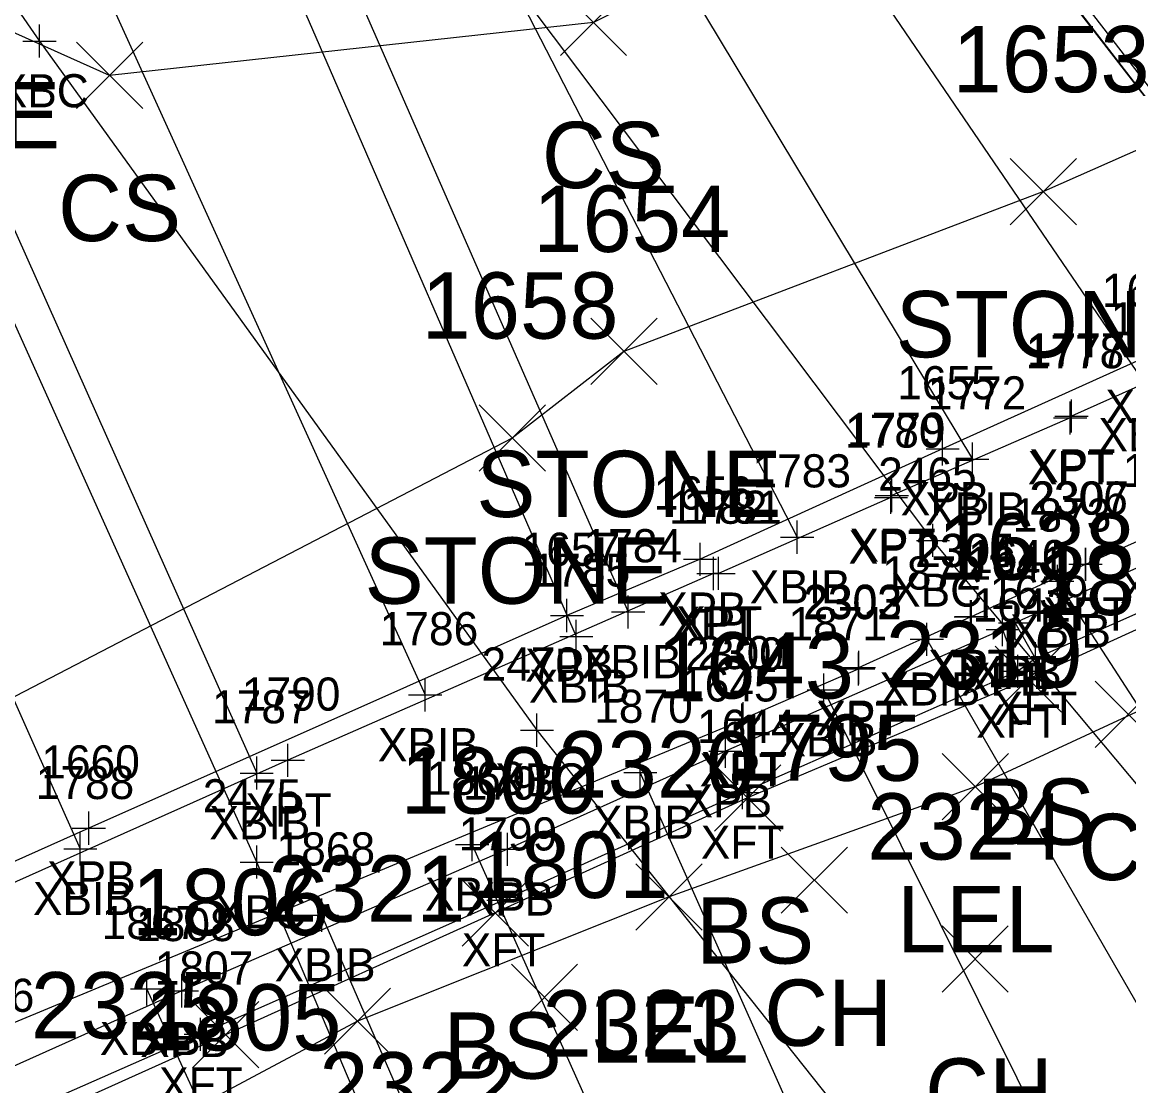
# Model space of a CAD drawing. Extents: x 1504228 to 1506103, y 437717 to 440106.
# Drawn here: x 1505201.55 to 1505234.96, y 438181.79 to 438213.89 of the extents above; entities that cross this region are included whole.
import ezdxf

# ---------------------------------------------------------------- set-up
doc = ezdxf.new("R2010")
doc.units = 0
for name, color, linetype in [('B_A', 7, 'Continuous'), ('B_I', 7, 'Continuous'), ('B_TIC', 7, 'Continuous'), ('BB', 7, 'Continuous'), ('BDC', 7, 'Continuous'), ('BELB', 7, 'Continuous'), ('BFT', 7, 'Continuous'), ('BSUBM', 7, 'Continuous'), ('L_A', 7, 'Continuous'), ('L_I', 7, 'Continuous'), ('L_TIC', 7, 'Continuous'), ('LARO', 7, 'Continuous'), ('LASF', 7, 'Continuous'), ('LELB', 7, 'Continuous')]:
    doc.layers.add(name, color=color, linetype=linetype)

msp = doc.modelspace()

# ---------------------------------------------------------------- linework, layer by layer
at = {"layer": 'B_TIC'}
for p, q in [((1505202.078, 438213.317), (1505202.153, 438213.317)), ((1505233.19, 438201.942), (1505233.265, 438201.942)), ((1505233.226, 438201.999), (1505233.302, 438201.999)), ((1505229.338, 438201.006), (1505229.414, 438201.006)), ((1505230.236, 438200.699), (1505230.311, 438200.699)), ((1505227.78, 438199.546), (1505227.855, 438199.546)), ((1505227.805, 438199.602), (1505227.88, 438199.602)), ((1505224.945, 438198.346), (1505225.021, 438198.346)), ((1505229.046, 438198.247), (1505229.121, 438198.247)), ((1505222.016, 438197.676), (1505222.092, 438197.676)), ((1505233.651, 438197.525), (1505233.726, 438197.525)), ((1505233.658, 438197.526), (1505233.733, 438197.526)), ((1505222.421, 438197.249), (1505222.497, 438197.249)), ((1505222.575, 438197.253), (1505222.651, 438197.253)), ((1505232.802, 438197.013), (1505232.877, 438197.013)), ((1505218, 438195.981), (1505218.075, 438195.981)), ((1505219.845, 438196.087), (1505219.921, 438196.087)), ((1505230.181, 438195.942), (1505230.257, 438195.942)), ((1505230.206, 438195.946), (1505230.282, 438195.946)), ((1505231.149, 438195.559), (1505231.225, 438195.559)), ((1505231.149, 438195.559), (1505231.225, 438195.559)), ((1505231.524, 438195.759), (1505231.599, 438195.759)), ((1505231.524, 438195.759), (1505231.599, 438195.759)), ((1505218.279, 438195.351), (1505218.355, 438195.351)), ((1505228.861, 438195.264), (1505228.936, 438195.264)), ((1505232.137, 438194.68), (1505232.212, 438194.68)), ((1505232.137, 438194.68), (1505232.212, 438194.68)), ((1505226.797, 438194.369), (1505226.872, 438194.369)), ((1505226.809, 438194.411), (1505226.885, 438194.411)), ((1505231.61, 438194.296), (1505231.685, 438194.296)), ((1505231.61, 438194.296), (1505231.685, 438194.296)), ((1505213.719, 438193.583), (1505213.795, 438193.583)), ((1505225.75, 438193.733), (1505225.825, 438193.733)), ((1505223.28, 438192.822), (1505223.356, 438192.822)), ((1505223.322, 438192.862), (1505223.397, 438192.862)), ((1505217.092, 438192.519), (1505217.168, 438192.519)), ((1505222.782, 438191.886), (1505222.857, 438191.886)), ((1505209.574, 438191.61), (1505209.65, 438191.61)), ((1505208.633, 438191.227), (1505208.709, 438191.227)), ((1505220.211, 438191.242), (1505220.286, 438191.242)), ((1505223.293, 438190.638), (1505223.369, 438190.638)), ((1505203.568, 438189.562), (1505203.643, 438189.562)), ((1505203.307, 438188.941), (1505203.383, 438188.941)), ((1505215.139, 438189.07), (1505215.214, 438189.07)), ((1505216.203, 438188.925), (1505216.278, 438188.925)), ((1505208.634, 438188.54), (1505208.71, 438188.54)), ((1505216.08, 438187.39), (1505216.155, 438187.39)), ((1505210.602, 438186.937), (1505210.678, 438186.937)), ((1505205.322, 438184.714), (1505205.397, 438184.714)), ((1505206.377, 438184.654), (1505206.453, 438184.654)), ((1505206.942, 438183.343), (1505207.017, 438183.343))]:
    msp.add_line(p, q, dxfattribs=at)
for points in [[(1505202.074, 438212.817), (1505202.074, 438213.817)], [(1505201.574, 438213.317), (1505202.574, 438213.317)], [(1505233.223, 438201.499), (1505233.223, 438202.499)], [(1505233.186, 438201.442), (1505233.186, 438202.442)], [(1505232.686, 438201.942), (1505233.686, 438201.942)], [(1505232.723, 438201.999), (1505233.723, 438201.999)], [(1505229.335, 438200.506), (1505229.335, 438201.506)], [(1505230.232, 438200.199), (1505230.232, 438201.199)], [(1505228.835, 438201.006), (1505229.835, 438201.006)], [(1505229.732, 438200.699), (1505230.732, 438200.699)], [(1505227.776, 438199.046), (1505227.776, 438200.046)], [(1505227.801, 438199.102), (1505227.801, 438200.102)], [(1505227.276, 438199.546), (1505228.276, 438199.546)], [(1505227.301, 438199.602), (1505228.301, 438199.602)], [(1505224.942, 438197.846), (1505224.942, 438198.846)], [(1505229.042, 438197.747), (1505229.042, 438198.747)], [(1505222.013, 438197.176), (1505222.013, 438198.176)], [(1505224.442, 438198.346), (1505225.442, 438198.346)], [(1505228.542, 438198.247), (1505229.542, 438198.247)], [(1505233.647, 438197.025), (1505233.647, 438198.025)], [(1505233.654, 438197.026), (1505233.654, 438198.026)], [(1505221.513, 438197.676), (1505222.513, 438197.676)], [(1505222.418, 438196.749), (1505222.418, 438197.749)], [(1505222.572, 438196.753), (1505222.572, 438197.753)], [(1505232.798, 438196.513), (1505232.798, 438197.513)], [(1505233.147, 438197.525), (1505234.147, 438197.525)], [(1505233.154, 438197.526), (1505234.154, 438197.526)], [(1505221.918, 438197.249), (1505222.918, 438197.249)], [(1505222.072, 438197.253), (1505223.072, 438197.253)], [(1505232.298, 438197.013), (1505233.298, 438197.013)], [(1505217.996, 438195.481), (1505217.996, 438196.481)], [(1505219.842, 438195.587), (1505219.842, 438196.587)], [(1505230.178, 438195.442), (1505230.178, 438196.442)], [(1505230.203, 438195.446), (1505230.203, 438196.446)], [(1505231.52, 438195.259), (1505231.52, 438196.259)], [(1505231.52, 438195.259), (1505231.52, 438196.259)], [(1505217.496, 438195.981), (1505218.496, 438195.981)], [(1505218.276, 438194.851), (1505218.276, 438195.851)], [(1505219.342, 438196.087), (1505220.342, 438196.087)], [(1505229.678, 438195.942), (1505230.678, 438195.942)], [(1505229.703, 438195.946), (1505230.703, 438195.946)], [(1505231.146, 438195.059), (1505231.146, 438196.059)], [(1505231.146, 438195.059), (1505231.146, 438196.059)], [(1505228.857, 438194.764), (1505228.857, 438195.764)], [(1505230.646, 438195.559), (1505231.646, 438195.559)], [(1505230.646, 438195.559), (1505231.646, 438195.559)], [(1505231.02, 438195.759), (1505232.02, 438195.759)], [(1505231.02, 438195.759), (1505232.02, 438195.759)], [(1505217.776, 438195.351), (1505218.776, 438195.351)], [(1505228.357, 438195.264), (1505229.357, 438195.264)], [(1505232.133, 438194.18), (1505232.133, 438195.18)], [(1505232.133, 438194.18), (1505232.133, 438195.18)], [(1505226.793, 438193.869), (1505226.793, 438194.869)], [(1505226.806, 438193.911), (1505226.806, 438194.911)], [(1505231.606, 438193.796), (1505231.606, 438194.796)], [(1505231.606, 438193.796), (1505231.606, 438194.796)], [(1505231.633, 438194.68), (1505232.633, 438194.68)], [(1505231.633, 438194.68), (1505232.633, 438194.68)], [(1505225.746, 438193.233), (1505225.746, 438194.233)], [(1505226.293, 438194.369), (1505227.293, 438194.369)], [(1505226.306, 438194.411), (1505227.306, 438194.411)], [(1505231.106, 438194.296), (1505232.106, 438194.296)], [(1505231.106, 438194.296), (1505232.106, 438194.296)], [(1505213.716, 438193.083), (1505213.716, 438194.083)], [(1505213.216, 438193.583), (1505214.216, 438193.583)], [(1505225.246, 438193.733), (1505226.246, 438193.733)], [(1505223.277, 438192.322), (1505223.277, 438193.322)], [(1505223.318, 438192.362), (1505223.318, 438193.362)], [(1505217.089, 438192.019), (1505217.089, 438193.019)], [(1505222.777, 438192.822), (1505223.777, 438192.822)], [(1505222.818, 438192.862), (1505223.818, 438192.862)], [(1505216.589, 438192.519), (1505217.589, 438192.519)], [(1505209.571, 438191.11), (1505209.571, 438192.11)], [(1505222.778, 438191.386), (1505222.778, 438192.386)], [(1505222.278, 438191.886), (1505223.278, 438191.886)], [(1505208.63, 438190.727), (1505208.63, 438191.727)], [(1505209.071, 438191.61), (1505210.071, 438191.61)], [(1505220.207, 438190.742), (1505220.207, 438191.742)], [(1505208.13, 438191.227), (1505209.13, 438191.227)], [(1505219.707, 438191.242), (1505220.707, 438191.242)], [(1505223.29, 438190.138), (1505223.29, 438191.138)], [(1505222.79, 438190.638), (1505223.79, 438190.638)], [(1505203.564, 438189.062), (1505203.564, 438190.062)], [(1505203.064, 438189.562), (1505204.064, 438189.562)], [(1505203.304, 438188.441), (1505203.304, 438189.441)], [(1505215.135, 438188.57), (1505215.135, 438189.57)], [(1505216.199, 438188.425), (1505216.199, 438189.425)], [(1505202.804, 438188.941), (1505203.804, 438188.941)], [(1505208.631, 438188.04), (1505208.631, 438189.04)], [(1505214.635, 438189.07), (1505215.635, 438189.07)], [(1505215.699, 438188.925), (1505216.699, 438188.925)], [(1505208.131, 438188.54), (1505209.131, 438188.54)], [(1505216.076, 438186.89), (1505216.076, 438187.89)], [(1505210.599, 438186.437), (1505210.599, 438187.437)], [(1505215.576, 438187.39), (1505216.576, 438187.39)], [(1505210.099, 438186.937), (1505211.099, 438186.937)], [(1505205.318, 438184.214), (1505205.318, 438185.214)], [(1505206.374, 438184.154), (1505206.374, 438185.154)], [(1505204.818, 438184.714), (1505205.818, 438184.714)], [(1505205.874, 438184.654), (1505206.874, 438184.654)], [(1505206.938, 438182.843), (1505206.938, 438183.843)], [(1505206.438, 438183.343), (1505207.438, 438183.343)]]:
    msp.add_lwpolyline(points, dxfattribs=at)
at = {"layer": 'BB'}
for points in [[(1505212.21, 438241.584), (1505240.46, 438205.162)], [(1505209.818, 438240.537), (1505235.468, 438202.936)], [(1505206.972, 438239.295), (1505230.232, 438200.699)], [(1505204.463, 438238.12), (1505224.942, 438198.346)], [(1505201.879, 438237.041), (1505219.842, 438196.087)], [(1505200.413, 438236.44), (1505218.276, 438195.351)], [(1505195.278, 438234.141), (1505213.716, 438193.583)], [(1505190.469, 438231.914), (1505208.63, 438191.227)], [(1505185.111, 438229.788), (1505203.304, 438188.941)], [(1505257.379, 438159.077), (1505232.798, 438197.013)], [(1505251.441, 438156.129), (1505228.857, 438195.264)], [(1505245.599, 438153.876), (1505225.746, 438193.733)], [(1505238.272, 438150.725), (1505220.207, 438191.242)], [(1505233.176, 438148.763), (1505215.135, 438189.07)], [(1505228.522, 438145.721), (1505210.599, 438186.937)], [(1505224.014, 438143.855), (1505205.318, 438184.714)]]:
    msp.add_lwpolyline(points, dxfattribs=at)
at = {"layer": 'BDC'}
msp.add_lwpolyline([(1505211.925, 438243.921), (1505227.096, 438222.88), (1505239.823, 438206.409), (1505253.849, 438189.887), (1505268.071, 438174.436), (1505276.686, 438165.513)], dxfattribs=at)
at = {"layer": 'BELB'}
for points in [[(1505211.812, 438243.704), (1505226.972, 438222.631), (1505239.63, 438206.209), (1505253.732, 438189.745), (1505267.938, 438174.29), (1505276.516, 438165.316)], [(1505262.808, 438159.474), (1505244.884, 438179.311), (1505229.042, 438198.247), (1505213.306, 438219.16), (1505200.113, 438237.757)], [(1505189.093, 438232.07), (1505202.074, 438213.317), (1505217.089, 438192.519), (1505234.002, 438171.224), (1505249.231, 438153.134)], [(1505227.121, 438143.057), (1505216.699, 438169.498), (1505208.631, 438188.54), (1505199.093, 438209.718)]]:
    msp.add_lwpolyline(points, dxfattribs=at)
at = {"layer": 'BFT'}
for points in [[(1505252.998, 438208.079), (1505252.263, 438206.145), (1505250.763, 438202.931), (1505232.133, 438194.68), (1505231.606, 438194.296), (1505223.29, 438190.638), (1505216.076, 438187.39), (1505206.938, 438183.343), (1505196.92, 438178.938), (1505191.516, 438180.897), (1505192.342, 438183.974)], [(1505231.146, 438195.559), (1505231.606, 438194.296)], [(1505232.133, 438194.68), (1505231.52, 438195.759)]]:
    msp.add_lwpolyline(points, dxfattribs=at)
at = {"layer": 'BSUBM'}
for points in [[(1505251.673, 438208.67), (1505250, 438209.507), (1505248.317, 438209.426), (1505235.511, 438203.792), (1505229.335, 438201.006), (1505222.013, 438197.676), (1505217.996, 438195.981), (1505203.564, 438189.562), (1505194.582, 438185.548), (1505193.788, 438184.98), (1505193.081, 438183.722)], [(1505249.605, 438208.929), (1505243.055, 438206.301), (1505242.97, 438206.167), (1505238.27, 438204.261), (1505238.196, 438204.221), (1505233.223, 438201.999), (1505233.186, 438201.942), (1505227.801, 438199.602), (1505227.776, 438199.546), (1505222.572, 438197.253), (1505222.418, 438197.249), (1505209.571, 438191.61), (1505197.655, 438186.296)], [(1505251.673, 438208.67), (1505252.263, 438206.145), (1505250.569, 438204.342), (1505231.52, 438195.759), (1505231.146, 438195.559), (1505222.778, 438191.886), (1505216.199, 438188.925), (1505206.374, 438184.654), (1505196.87, 438180.394), (1505195.929, 438180.154), (1505194.33, 438180.389), (1505192.951, 438181.893), (1505193.081, 438183.722)], [(1505197.376, 438182.065), (1505223.277, 438192.822), (1505223.318, 438192.862), (1505226.793, 438194.369), (1505226.806, 438194.411), (1505230.178, 438195.942), (1505230.203, 438195.946), (1505233.647, 438197.525), (1505233.654, 438197.526), (1505237.025, 438199.027), (1505237.039, 438199.021), (1505240.477, 438200.603), (1505240.467, 438200.574), (1505244.674, 438202.443), (1505244.747, 438202.628)]]:
    msp.add_lwpolyline(points, dxfattribs=at)
at = {"layer": 'L_TIC'}
for points in [[(1505217.796, 438212.879), (1505219.796, 438214.879)], [(1505219.796, 438212.879), (1505217.796, 438214.879)], [(1505203.191, 438211.28), (1505205.191, 438213.28)], [(1505205.191, 438211.28), (1505203.191, 438213.28)], [(1505231.375, 438207.772), (1505233.375, 438209.772)], [(1505233.375, 438207.772), (1505231.375, 438209.772)], [(1505218.716, 438202.952), (1505220.716, 438204.952)], [(1505220.716, 438202.952), (1505218.716, 438204.952)], [(1505215.343, 438200.336), (1505217.343, 438202.336)], [(1505217.343, 438200.336), (1505215.343, 438202.336)], [(1505230.919, 438193.06), (1505232.919, 438195.06)], [(1505232.919, 438193.06), (1505230.919, 438195.06)], [(1505233.941, 438191.997), (1505235.941, 438193.997)], [(1505235.941, 438191.997), (1505233.941, 438193.997)], [(1505229.318, 438189.813), (1505231.318, 438191.813)], [(1505231.318, 438189.813), (1505229.318, 438191.813)], [(1505222.449, 438189.476), (1505224.449, 438191.476)], [(1505224.449, 438189.476), (1505222.449, 438191.476)], [(1505224.46, 438186.993), (1505226.46, 438188.993)], [(1505226.46, 438186.993), (1505224.46, 438188.993)], [(1505220.077, 438186.488), (1505222.077, 438188.488)], [(1505222.077, 438186.488), (1505220.077, 438188.488)], [(1505214.829, 438186.003), (1505216.829, 438188.003)], [(1505216.829, 438186.003), (1505214.829, 438188.003)], [(1505229.317, 438184.615), (1505231.317, 438186.615)], [(1505231.317, 438184.615), (1505229.317, 438186.615)], [(1505216.318, 438183.457), (1505218.318, 438185.457)], [(1505218.318, 438183.457), (1505216.318, 438185.457)], [(1505210.673, 438182.738), (1505212.673, 438184.738)], [(1505212.673, 438182.738), (1505210.673, 438184.738)], [(1505206.689, 438182.331), (1505208.689, 438184.331)], [(1505208.689, 438182.331), (1505206.689, 438184.331)]]:
    msp.add_lwpolyline(points, dxfattribs=at)
at = {"layer": 'LARO'}
msp.add_lwpolyline([(1505257.789, 438202.997), (1505250.211, 438200.467), (1505241.258, 438195.88), (1505230.318, 438190.813), (1505221.077, 438187.488), (1505211.673, 438183.738), (1505205.073, 438180.218), (1505196.112, 438175.447), (1505190.999, 438172.732), (1505182.993, 438174.698), (1505180.265, 438174.662)], dxfattribs=at)
at = {"layer": 'LASF'}
msp.add_lwpolyline([(1505231.536, 438240.553), (1505235.748, 438236.802), (1505232.624, 438230.462), (1505239.591, 438224.256), (1505247.096, 438215.294), (1505232.375, 438208.772), (1505219.716, 438203.952), (1505216.343, 438201.336), (1505195.139, 438190.329), (1505194.762, 438205.795)], dxfattribs=at)
at = {"layer": 'LELB'}
for points in [[(1505365.146, 438316.099), (1505353.966, 438296.236), (1505341.915, 438275.153), (1505332.016, 438262.134), (1505323.954, 438252.628), (1505313.563, 438242.629), (1505305.646, 438236.558), (1505295.746, 438229.78), (1505286.64, 438224.685), (1505273.677, 438216.738), (1505262.485, 438213.279), (1505253.251, 438208.207), (1505250.962, 438202.759), (1505231.919, 438194.06), (1505223.449, 438190.476), (1505215.829, 438187.003), (1505207.689, 438183.331), (1505196.859, 438178.456)], [(1505270.798, 438231.377), (1505256.305, 438221.751), (1505239.591, 438224.256), (1505218.796, 438213.879), (1505204.191, 438212.28), (1505197.941, 438215.08), (1505180.455, 438206.428)]]:
    msp.add_lwpolyline(points, dxfattribs=at)

# ---------------------------------------------------------------- texts
at = {"layer": 'B_A'}
for s, p in [('XBC', (1505200.811, 438211.317)), ('XPB', (1505234.248, 438201.792)), ('XBIB', (1505234.039, 438200.936)), ('XPT', (1505231.907, 438199.942)), ('XPT', (1505231.943, 438199.999)), ('XPB', (1505228.071, 438199.006)), ('XBIB', (1505228.803, 438198.699)), ('XPT', (1505226.497, 438197.546)), ('XPT', (1505226.522, 438197.602)), ('XBIB', (1505223.513, 438196.346)), ('XBC', (1505227.778, 438196.247)), ('XBIB', (1505234.691, 438196.358)), ('XPB', (1505220.749, 438195.676)), ('XPT', (1505232.368, 438195.525)), ('XPT', (1505232.375, 438195.526)), ('XPT', (1505221.138, 438195.249)), ('XPT', (1505221.292, 438195.253)), ('XBIB', (1505231.369, 438195.013)), ('XPB', (1505216.732, 438193.981)), ('XBIB', (1505218.412, 438194.087)), ('XPT', (1505228.898, 438193.942)), ('XPT', (1505228.923, 438193.946)), ('XPB', (1505229.882, 438193.559)), ('XFT', (1505229.89, 438193.559)), ('XPB', (1505230.256, 438193.759)), ('XFT', (1505230.264, 438193.759)), ('XBIB', (1505216.847, 438193.351)), ('XBIB', (1505227.428, 438193.264)), ('XFT', (1505230.878, 438192.68)), ('XFT', (1505230.878, 438192.68)), ('XPT', (1505225.514, 438192.369)), ('XPT', (1505225.526, 438192.411)), ('XFT', (1505230.35, 438192.296)), ('XFT', (1505230.35, 438192.296)), ('XBIB', (1505212.287, 438191.583)), ('XBIB', (1505224.317, 438191.733)), ('XPT', (1505221.997, 438190.822)), ('XPT', (1505222.039, 438190.862)), ('XBC', (1505215.825, 438190.519)), ('XPB', (1505221.514, 438189.886)), ('XPT', (1505208.291, 438189.61)), ('XBIB', (1505207.201, 438189.227)), ('XBIB', (1505218.778, 438189.242)), ('XFT', (1505222.034, 438188.638)), ('XPB', (1505202.3, 438187.562)), ('XBIB', (1505201.875, 438186.941)), ('XBIB', (1505213.706, 438187.07)), ('XPB', (1505214.935, 438186.925)), ('XBC', (1505207.367, 438186.54)), ('XFT', (1505214.82, 438185.39)), ('XBIB', (1505209.17, 438184.937)), ('XBIB', (1505203.889, 438182.714)), ('XPB', (1505205.11, 438182.654)), ('XFT', (1505205.683, 438181.343))]:
    msp.add_text(s, height=1, dxfattribs=at).set_placement(p)
at = {"layer": 'B_I'}
for s, p in [('1652', (1505234.141, 438205.292)), ('1771', (1505234.405, 438204.436)), ('1778', (1505231.84, 438203.442)), ('1777', (1505231.876, 438203.499)), ('1655', (1505227.965, 438202.506)), ('1772', (1505228.886, 438202.199)), ('1779', (1505226.451, 438201.102)), ('1780', (1505226.387, 438201.046)), ('1783', (1505223.595, 438199.846)), ('1874', (1505234.774, 438199.858)), ('2465', (1505227.389, 438199.747)), ('1656', (1505220.615, 438199.176)), ('2306', (1505231.95, 438199.025)), ('2307', (1505231.985, 438199.026)), ('1782', (1505221.072, 438198.749)), ('1781', (1505221.509, 438198.753)), ('1873', (1505231.452, 438198.513)), ('1657', (1505216.626, 438197.481)), ('1784', (1505218.495, 438197.587)), ('2304', (1505228.508, 438197.442)), ('2305', (1505228.534, 438197.446)), ('1640', (1505230.107, 438197.259)), ('1640', (1505230.107, 438197.259)), ('1785', (1505216.929, 438196.851)), ('1872', (1505227.511, 438196.764)), ('1641', (1505230.059, 438197.059)), ('1641', (1505230.059, 438197.059)), ('1639', (1505230.759, 438196.18)), ('1639', (1505230.759, 438196.18)), ('2302', (1505225.124, 438195.869)), ('2303', (1505225.136, 438195.911)), ('1642', (1505230.236, 438195.796)), ('1642', (1505230.236, 438195.796)), ('1871', (1505224.683, 438195.233)), ('1786', (1505212.342, 438195.083)), ('2300', (1505221.564, 438194.322)), ('2301', (1505221.933, 438194.362)), ('2470', (1505215.416, 438194.019)), ('1790', (1505208.181, 438193.11)), ('1645', (1505221.408, 438193.386)), ('1787', (1505207.283, 438192.727)), ('1870', (1505218.817, 438192.742)), ('1644', (1505221.92, 438192.138)), ('1660', (1505202.127, 438191.062)), ('1788', (1505201.957, 438190.441)), ('1869', (1505213.761, 438190.57)), ('1798', (1505214.853, 438190.425)), ('2475', (1505207.001, 438190.04)), ('1799', (1505214.726, 438188.89)), ('1868', (1505209.229, 438188.437)), ('1867', (1505203.948, 438186.214)), ('1808', (1505204.988, 438186.154)), ('1807', (1505205.553, 438184.843)), ('1866', (1505198.942, 438184.019))]:
    msp.add_text(s, height=1, dxfattribs=at).set_placement(p)
at = {"layer": 'L_A'}
for s, p in [('STONE', (1505193.484, 438210.08)), ('CS', (1505217.237, 438208.879)), ('CS', (1505202.632, 438207.28)), ('STONE', (1505227.918, 438203.772)), ('STONE', (1505215.259, 438198.952)), ('STONE', (1505211.886, 438196.336)), ('BS', (1505230.36, 438189.06)), ('CH', (1505233.429, 438187.997)), ('LEL', (1505227.956, 438185.813)), ('BS', (1505221.89, 438185.476)), ('CH', (1505223.949, 438182.993)), ('LEL', (1505218.715, 438182.488)), ('BS', (1505214.27, 438182.003)), ('CH', (1505228.805, 438180.615))]:
    msp.add_text(s, height=2, dxfattribs=at).set_placement(p)
at = {"layer": 'L_I'}
for s, p in [('1653', (1505229.634, 438211.772)), ('1654', (1505216.976, 438206.952)), ('1658', (1505213.603, 438204.336)), ('1638', (1505229.179, 438197.06)), ('1802', (1505232.169, 438195.997)), ('2319', (1505227.617, 438193.813)), ('1643', (1505220.709, 438193.476)), ('1795', (1505222.768, 438190.993)), ('2320', (1505217.731, 438190.488)), ('1800', (1505212.971, 438190.003)), ('2324', (1505227.057, 438188.615)), ('1801', (1505215.114, 438187.457)), ('2321', (1505208.98, 438186.738)), ('1806', (1505204.863, 438186.331)), ('2325', (1505201.813, 438183.218)), ('1805', (1505205.24, 438182.856)), ('2323', (1505217.255, 438182.671)), ('2322', (1505210.518, 438180.801))]:
    msp.add_text(s, height=2, dxfattribs=at).set_placement(p)

doc.saveas('drawing.dxf')
